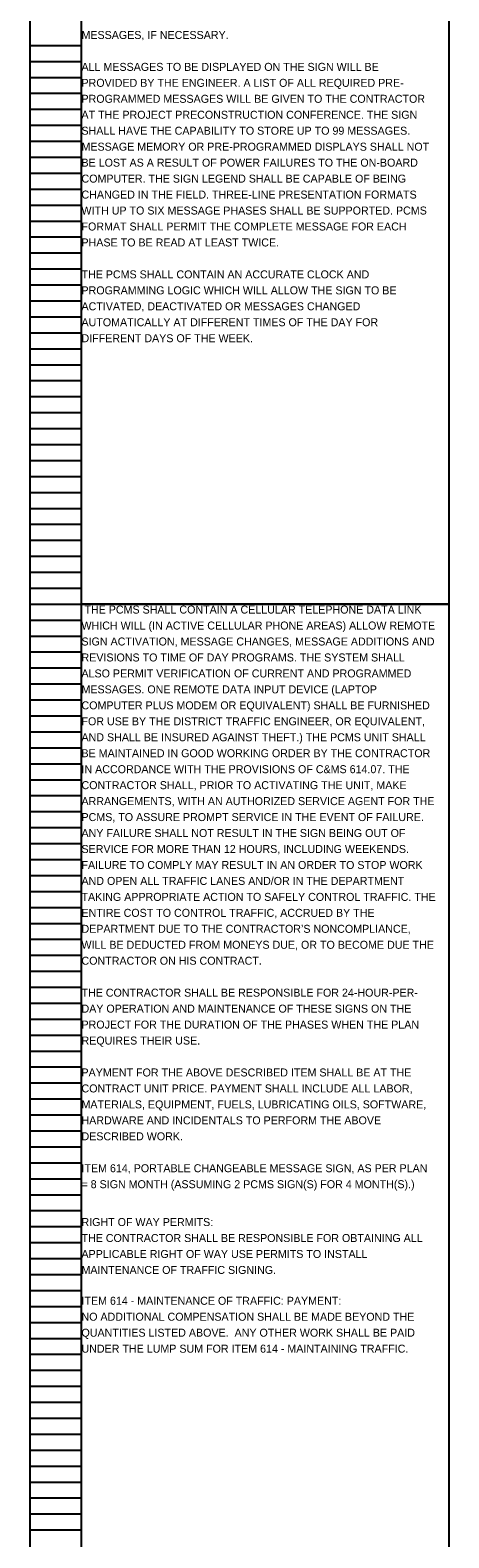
# Model space of a CAD drawing. Extents: x 16463 to 16500, y 5400 to 5823.
# Drawn here: x 16463.05 to 16470.39, y 5585.33 to 5611.78 of the extents above; entities that cross this region are included whole.
import ezdxf

# ---------------------------------------------------------------- set-up
doc = ezdxf.new("R2010")
doc.units = 0
for name, color, linetype in [('Default', 7, 'Continuous'), ('SC_Scratch1', 7, 'Continuous'), ('SH_Data', 7, 'Continuous')]:
    doc.layers.add(name, color=color, linetype=linetype)

msp = doc.modelspace()

# ---------------------------------------------------------------- linework, layer by layer
at = {"layer": 'SC_Scratch1'}
for points in [[(16463.949, 5621.872), (16470.389, 5621.872), (16470.389, 5601.712), (16463.949, 5601.712)], [(16463.949, 5601.712), (16470.389, 5601.712), (16470.389, 5581.552), (16463.949, 5581.552)]]:
    msp.add_lwpolyline(points, close=True, dxfattribs=at)
at = {"layer": 'SH_Data'}
for p, q in [((16463.049, 5601.712), (16463.049, 5621.872)), ((16463.949, 5601.712), (16463.949, 5621.872)), ((16463.049, 5611.512), (16463.949, 5611.512)), ((16463.049, 5611.232), (16463.949, 5611.232)), ((16463.049, 5610.952), (16463.949, 5610.952)), ((16463.049, 5610.672), (16463.949, 5610.672)), ((16463.049, 5610.392), (16463.949, 5610.392)), ((16463.049, 5610.112), (16463.949, 5610.112)), ((16463.049, 5609.832), (16463.949, 5609.832)), ((16463.049, 5609.552), (16463.949, 5609.552)), ((16463.049, 5609.272), (16463.949, 5609.272)), ((16463.049, 5608.992), (16463.949, 5608.992)), ((16463.049, 5608.712), (16463.949, 5608.712)), ((16463.049, 5608.432), (16463.949, 5608.432)), ((16463.049, 5608.152), (16463.949, 5608.152)), ((16463.049, 5607.872), (16463.949, 5607.872)), ((16463.049, 5607.592), (16463.949, 5607.592)), ((16463.049, 5607.312), (16463.949, 5607.312)), ((16463.049, 5607.032), (16463.949, 5607.032)), ((16463.049, 5606.752), (16463.949, 5606.752)), ((16463.049, 5606.472), (16463.949, 5606.472)), ((16463.049, 5606.192), (16463.949, 5606.192)), ((16463.049, 5605.912), (16463.949, 5605.912)), ((16463.049, 5605.632), (16463.949, 5605.632)), ((16463.049, 5605.352), (16463.949, 5605.352)), ((16463.049, 5605.072), (16463.949, 5605.072)), ((16463.049, 5604.792), (16463.949, 5604.792)), ((16463.049, 5604.512), (16463.949, 5604.512)), ((16463.049, 5604.232), (16463.949, 5604.232)), ((16463.049, 5603.952), (16463.949, 5603.952)), ((16463.049, 5603.672), (16463.949, 5603.672)), ((16463.049, 5603.392), (16463.949, 5603.392)), ((16463.049, 5603.112), (16463.949, 5603.112)), ((16463.049, 5602.832), (16463.949, 5602.832)), ((16463.049, 5602.552), (16463.949, 5602.552)), ((16463.049, 5602.272), (16463.949, 5602.272)), ((16463.049, 5601.992), (16463.949, 5601.992)), ((16463.049, 5581.552), (16463.049, 5601.712)), ((16463.049, 5601.712), (16463.949, 5601.712)), ((16463.049, 5601.712), (16463.949, 5601.712)), ((16463.949, 5581.552), (16463.949, 5601.712)), ((16463.049, 5601.432), (16463.949, 5601.432)), ((16463.049, 5601.152), (16463.949, 5601.152)), ((16463.049, 5600.872), (16463.949, 5600.872)), ((16463.049, 5600.592), (16463.949, 5600.592)), ((16463.049, 5600.312), (16463.949, 5600.312)), ((16463.049, 5600.032), (16463.949, 5600.032)), ((16463.049, 5599.752), (16463.949, 5599.752)), ((16463.049, 5599.472), (16463.949, 5599.472)), ((16463.049, 5599.192), (16463.949, 5599.192)), ((16463.049, 5598.912), (16463.949, 5598.912)), ((16463.049, 5598.632), (16463.949, 5598.632)), ((16463.049, 5598.352), (16463.949, 5598.352)), ((16463.049, 5598.072), (16463.949, 5598.072)), ((16463.049, 5597.792), (16463.949, 5597.792)), ((16463.049, 5597.512), (16463.949, 5597.512)), ((16463.049, 5597.232), (16463.949, 5597.232)), ((16463.049, 5596.952), (16463.949, 5596.952)), ((16463.049, 5596.672), (16463.949, 5596.672)), ((16463.049, 5596.392), (16463.949, 5596.392)), ((16463.049, 5596.112), (16463.949, 5596.112)), ((16463.049, 5595.832), (16463.949, 5595.832)), ((16463.049, 5595.552), (16463.949, 5595.552)), ((16463.049, 5595.272), (16463.949, 5595.272)), ((16463.049, 5594.992), (16463.949, 5594.992)), ((16463.049, 5594.712), (16463.949, 5594.712)), ((16463.049, 5594.432), (16463.949, 5594.432)), ((16463.049, 5594.152), (16463.949, 5594.152)), ((16463.049, 5593.872), (16463.949, 5593.872)), ((16463.049, 5593.592), (16463.949, 5593.592)), ((16463.049, 5593.312), (16463.949, 5593.312)), ((16463.049, 5593.032), (16463.949, 5593.032)), ((16463.049, 5592.752), (16463.949, 5592.752)), ((16463.049, 5592.472), (16463.949, 5592.472)), ((16463.049, 5592.192), (16463.949, 5592.192)), ((16463.049, 5591.912), (16463.949, 5591.912)), ((16463.049, 5591.632), (16463.949, 5591.632)), ((16463.049, 5591.352), (16463.949, 5591.352)), ((16463.049, 5591.072), (16463.949, 5591.072)), ((16463.049, 5590.792), (16463.949, 5590.792)), ((16463.049, 5590.512), (16463.949, 5590.512)), ((16463.049, 5590.232), (16463.949, 5590.232)), ((16463.049, 5589.952), (16463.949, 5589.952)), ((16463.049, 5589.672), (16463.949, 5589.672)), ((16463.049, 5589.392), (16463.949, 5589.392)), ((16463.049, 5589.112), (16463.949, 5589.112)), ((16463.049, 5588.832), (16463.949, 5588.832)), ((16463.049, 5588.552), (16463.949, 5588.552)), ((16463.049, 5588.272), (16463.949, 5588.272)), ((16463.049, 5587.992), (16463.949, 5587.992)), ((16463.049, 5587.712), (16463.949, 5587.712)), ((16463.049, 5587.432), (16463.949, 5587.432)), ((16463.049, 5587.152), (16463.949, 5587.152)), ((16463.049, 5586.872), (16463.949, 5586.872)), ((16463.049, 5586.592), (16463.949, 5586.592)), ((16463.049, 5586.312), (16463.949, 5586.312)), ((16463.049, 5586.032), (16463.949, 5586.032)), ((16463.049, 5585.752), (16463.949, 5585.752)), ((16463.049, 5585.472), (16463.949, 5585.472))]:
    msp.add_line(p, q, dxfattribs=at)

# ---------------------------------------------------------------- texts
at = {"layer": 'Default'}
for s, p in [('MESSAGES, IF NECESSARY.', (16463.949, 5611.626)), ('ALL MESSAGES TO BE DISPLAYED ON THE SIGN WILL BE ', (16463.949, 5611.066)), ('PROVIDED BY THE ENGINEER. A LIST OF ALL REQUIRED PRE-', (16463.949, 5610.786)), ('PROGRAMMED MESSAGES WILL BE GIVEN TO THE CONTRACTOR ', (16463.949, 5610.506)), ('AT THE PROJECT PRECONSTRUCTION CONFERENCE. THE SIGN ', (16463.949, 5610.226)), ('SHALL HAVE THE CAPABILITY TO STORE UP TO 99 MESSAGES. ', (16463.949, 5609.946)), ('MESSAGE MEMORY OR PRE-PROGRAMMED DISPLAYS SHALL NOT ', (16463.949, 5609.666)), ('BE LOST AS A RESULT OF POWER FAILURES TO THE ON-BOARD ', (16463.949, 5609.386)), ('COMPUTER. THE SIGN LEGEND SHALL BE CAPABLE OF BEING ', (16463.949, 5609.106)), ('CHANGED IN THE FIELD. THREE-LINE PRESENTATION FORMATS ', (16463.949, 5608.826)), ('WITH UP TO SIX MESSAGE PHASES SHALL BE SUPPORTED. PCMS ', (16463.949, 5608.546)), ('FORMAT SHALL PERMIT THE COMPLETE MESSAGE FOR EACH ', (16463.949, 5608.266)), ('PHASE TO BE READ AT LEAST TWICE. ', (16463.949, 5607.986)), ('THE PCMS SHALL CONTAIN AN ACCURATE CLOCK AND ', (16463.949, 5607.426)), ('PROGRAMMING LOGIC WHICH WILL ALLOW THE SIGN TO BE ', (16463.949, 5607.146)), ('ACTIVATED, DEACTIVATED OR MESSAGES CHANGED ', (16463.949, 5606.866)), ('AUTOMATICALLY AT DIFFERENT TIMES OF THE DAY FOR ', (16463.949, 5606.586)), ('DIFFERENT DAYS OF THE WEEK.', (16463.949, 5606.306)), (' THE PCMS SHALL CONTAIN A CELLULAR TELEPHONE DATA LINK ', (16463.949, 5601.546)), ('WHICH WILL (IN ACTIVE CELLULAR PHONE AREAS) ALLOW REMOTE ', (16463.949, 5601.266)), ('SIGN ACTIVATION, MESSAGE CHANGES, MESSAGE ADDITIONS AND ', (16463.949, 5600.986)), ('REVISIONS TO TIME OF DAY PROGRAMS. THE SYSTEM SHALL ', (16463.949, 5600.706)), ('ALSO PERMIT VERIFICATION OF CURRENT AND PROGRAMMED ', (16463.949, 5600.426)), ('MESSAGES. ONE REMOTE DATA INPUT DEVICE (LAPTOP ', (16463.949, 5600.146)), ('COMPUTER PLUS MODEM OR EQUIVALENT) SHALL BE FURNISHED ', (16463.949, 5599.866)), ('FOR USE BY THE DISTRICT TRAFFIC ENGINEER, OR EQUIVALENT, ', (16463.949, 5599.586)), ('AND SHALL BE INSURED AGAINST THEFT.) THE PCMS UNIT SHALL ', (16463.949, 5599.306)), ('BE MAINTAINED IN GOOD WORKING ORDER BY THE CONTRACTOR ', (16463.949, 5599.026)), ('IN ACCORDANCE WITH THE PROVISIONS OF C&MS 614.07. THE ', (16463.949, 5598.746)), ('CONTRACTOR SHALL, PRIOR TO ACTIVATING THE UNIT, MAKE ', (16463.949, 5598.466)), ('ARRANGEMENTS, WITH AN AUTHORIZED SERVICE AGENT FOR THE ', (16463.949, 5598.186)), ('PCMS, TO ASSURE PROMPT SERVICE IN THE EVENT OF FAILURE. ', (16463.949, 5597.906)), ('ANY FAILURE SHALL NOT RESULT IN THE SIGN BEING OUT OF ', (16463.949, 5597.626)), ('SERVICE FOR MORE THAN 12 HOURS, INCLUDING WEEKENDS. ', (16463.949, 5597.346)), ('FAILURE TO COMPLY MAY RESULT IN AN ORDER TO STOP WORK ', (16463.949, 5597.066)), ('AND OPEN ALL TRAFFIC LANES AND/OR IN THE DEPARTMENT ', (16463.949, 5596.786)), ('TAKING APPROPRIATE ACTION TO SAFELY CONTROL TRAFFIC. THE ', (16463.949, 5596.506)), ('ENTIRE COST TO CONTROL TRAFFIC, ACCRUED BY THE ', (16463.949, 5596.226)), ('DEPARTMENT DUE TO THE CONTRACTOR’S NONCOMPLIANCE, ', (16463.949, 5595.946)), ('WILL BE DEDUCTED FROM MONEYS DUE, OR TO BECOME DUE THE ', (16463.949, 5595.666)), ('CONTRACTOR ON HIS CONTRACT.', (16463.949, 5595.386)), ('THE CONTRACTOR SHALL BE RESPONSIBLE FOR 24-HOUR-PER-', (16463.949, 5594.826)), ('DAY OPERATION AND MAINTENANCE OF THESE SIGNS ON THE ', (16463.949, 5594.546)), ('PROJECT FOR THE DURATION OF THE PHASES WHEN THE PLAN ', (16463.949, 5594.266)), ('REQUIRES THEIR USE. ', (16463.949, 5593.986)), ('PAYMENT FOR THE ABOVE DESCRIBED ITEM SHALL BE AT THE ', (16463.949, 5593.426)), ('CONTRACT UNIT PRICE. PAYMENT SHALL INCLUDE ALL LABOR, ', (16463.949, 5593.146)), ('MATERIALS, EQUIPMENT, FUELS, LUBRICATING OILS, SOFTWARE, ', (16463.949, 5592.866)), ('HARDWARE AND INCIDENTALS TO PERFORM THE ABOVE ', (16463.949, 5592.586)), ('DESCRIBED WORK. ', (16463.949, 5592.306)), ('ITEM 614, PORTABLE CHANGEABLE MESSAGE SIGN, AS PER PLAN ', (16463.949, 5591.746)), ('= 8 SIGN MONTH (ASSUMING 2 PCMS SIGN(S) FOR 4 MONTH(S).)', (16463.949, 5591.466)), ('RIGHT OF WAY PERMITS:', (16463.949, 5590.802)), ('THE CONTRACTOR SHALL BE RESPONSIBLE FOR OBTAINING ALL ', (16463.949, 5590.522)), ('APPLICABLE RIGHT OF WAY USE PERMITS TO INSTALL ', (16463.949, 5590.242)), ('MAINTENANCE OF TRAFFIC SIGNING.', (16463.949, 5589.962)), ('ITEM 614 - MAINTENANCE OF TRAFFIC: PAYMENT:', (16463.949, 5589.421)), ('NO ADDITIONAL COMPENSATION SHALL BE MADE BEYOND THE ', (16463.949, 5589.141)), ('QUANTITIES LISTED ABOVE.  ANY OTHER WORK SHALL BE PAID ', (16463.949, 5588.861)), ('UNDER THE LUMP SUM FOR ITEM 614 - MAINTAINING TRAFFIC.', (16463.949, 5588.581))]:
    msp.add_text(s, height=0.14, dxfattribs=at).set_placement(p)

doc.saveas('drawing.dxf')
